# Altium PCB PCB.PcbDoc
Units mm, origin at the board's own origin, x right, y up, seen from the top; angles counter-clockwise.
Board outline 41 x 25.36 mm, 2 copper layers (TOP, BOTTOM), stack 1.586 mm thick; 29 components, 7 nets, 60 pads, 41 vias.
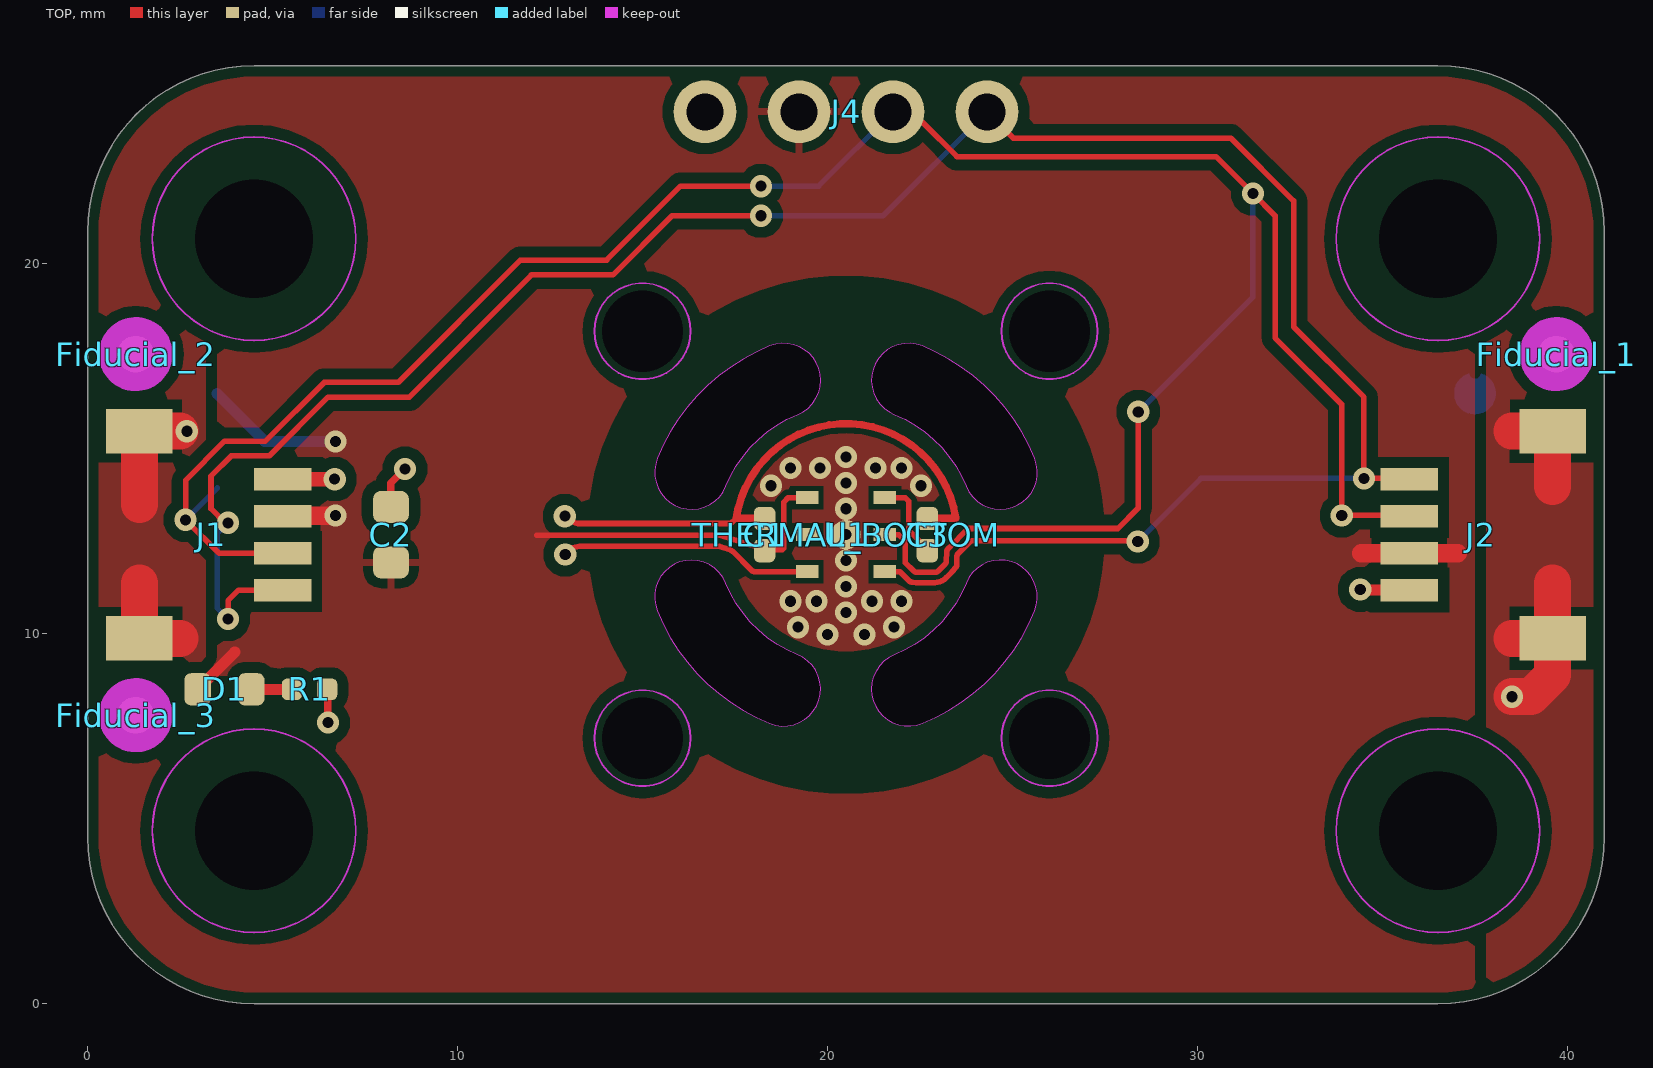
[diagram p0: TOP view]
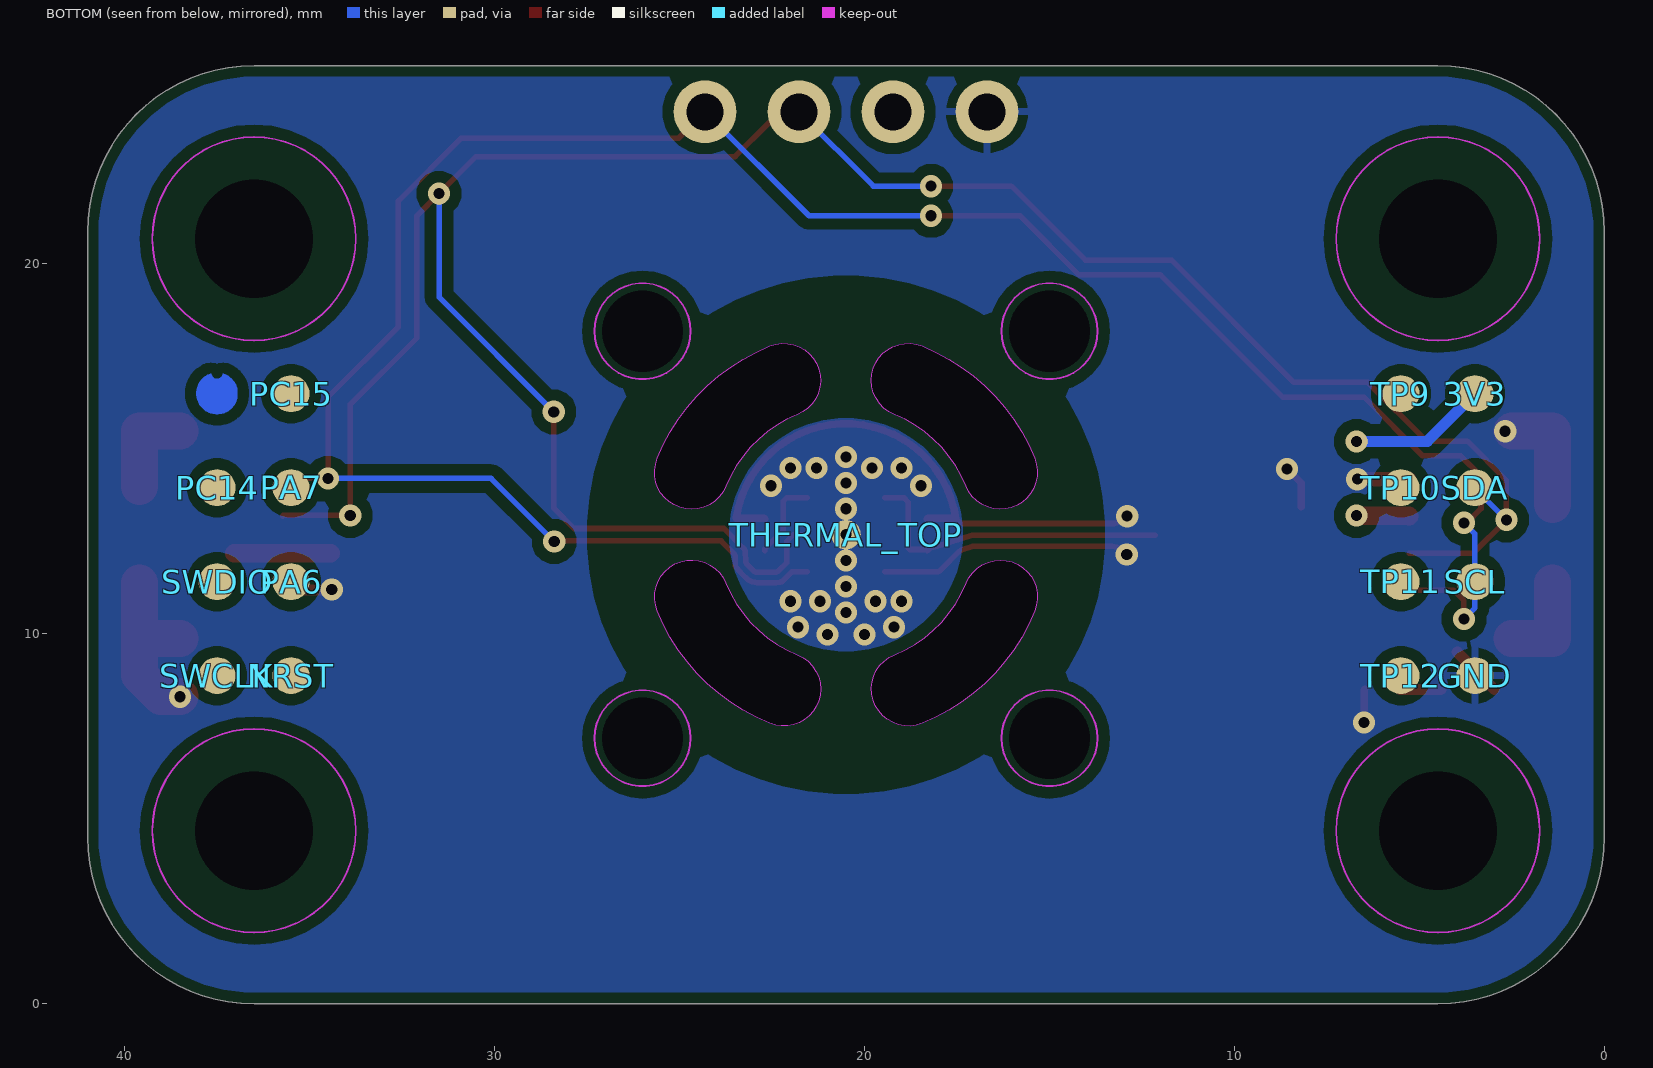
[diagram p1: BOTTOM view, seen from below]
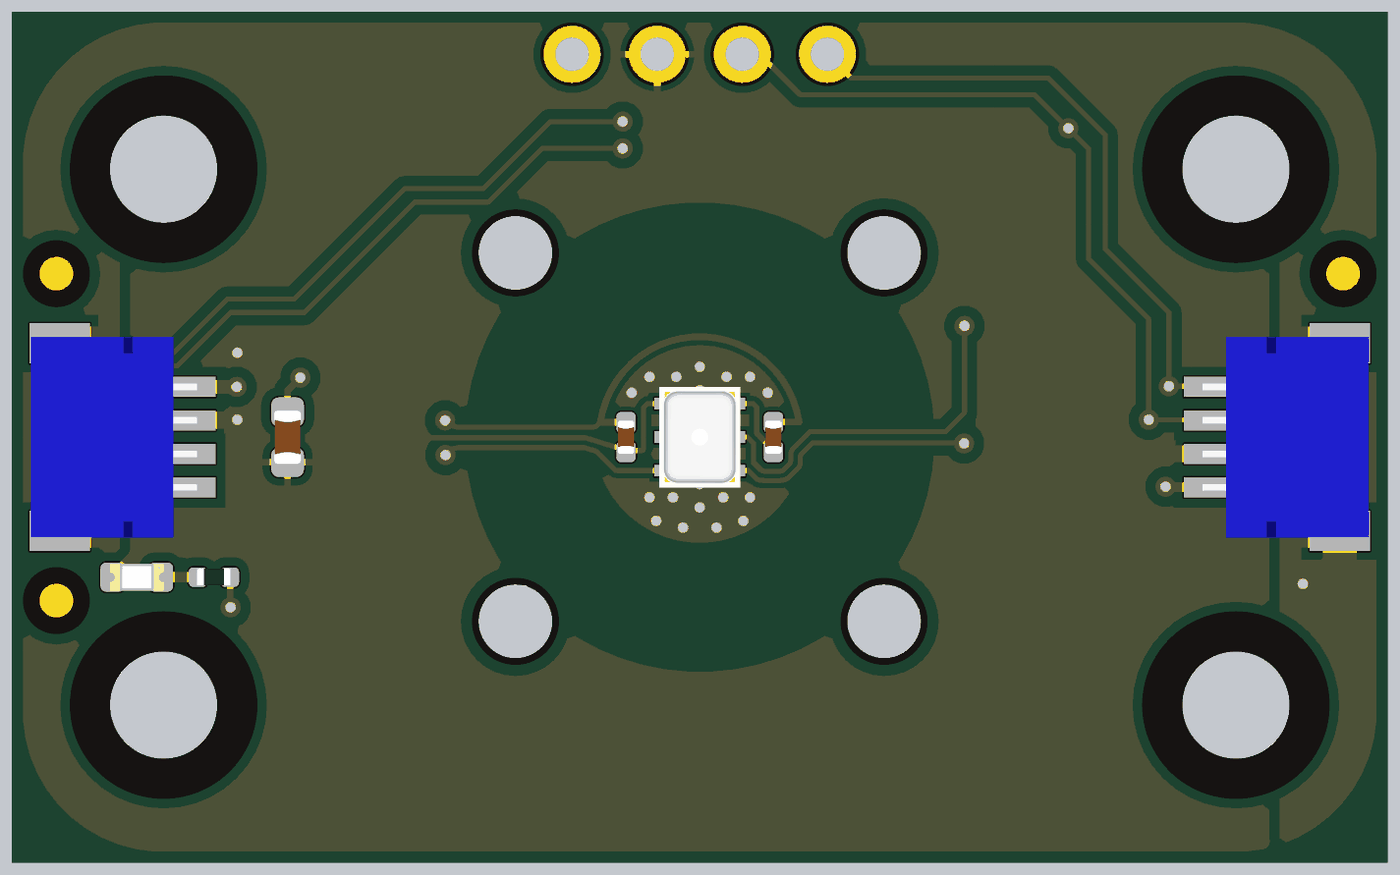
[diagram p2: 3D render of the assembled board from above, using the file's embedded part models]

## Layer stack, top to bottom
Top Solder: solder mask 0.01, Solder Resist, Dk 3.5
TOP: signal copper 0.018
Dielectric: core 1.55, FR-4, Dk 4.8
BOTTOM: signal copper 0.018
Bottom Solder: solder mask 0.01, Solder Resist, Dk 3.5

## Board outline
0,4.5 ccw(c4.5,4.5) 4.5,0 36.5,0 ccw(c36.5,4.5) 41,4.5 41,20.86 ccw(c36.5,20.86) 36.5,25.36 4.5,25.36 ccw(c4.5,20.86) 0,20.86
cut-out: 25.6,10.62 ccw(c24.672,10.994) 23.745,11.369 cw(c20.5,12.68) 21.811,9.435 ccw(c22.186,8.508) 21.185,8.508 ccw(c22.186,8.508) 22.561,7.58 ccw(c20.5,12.68)
cut-out: 22.561,17.78 ccw(c22.186,16.852) 21.811,15.925 cw(c20.5,12.68) 23.745,13.991 ccw(c24.672,14.366) 24.672,13.365 ccw(c24.672,14.366) 25.6,14.74 ccw(c20.5,12.68)
cut-out: 18.44,7.58 ccw(c18.814,8.508) 19.189,9.435 cw(c20.5,12.68) 17.255,11.369 ccw(c16.328,10.994) 16.328,11.995 ccw(c16.328,10.994) 15.4,10.62 ccw(c20.5,12.68)
cut-out: 15.4,14.74 ccw(c16.328,14.366) 17.255,13.991 cw(c20.5,12.68) 19.189,15.925 ccw(c18.814,16.852) 19.815,16.852 ccw(c18.814,16.852) 18.44,17.78 ccw(c20.5,12.68)

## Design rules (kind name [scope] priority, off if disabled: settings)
BoardOutlineClearance Mousebites [(ObjectKind = 'Pad') And (Name = 'Free-MOUSEBITE')] p1: gap=0 ignorepadtopadclearanceinfootprint=FALSE
BoardOutlineClearance Silks [(OnLayer('Top Overlay') OR OnLayer('Bottom Overlay'))] p2: gap=0 ignorepadtopadclearanceinfootprint=FALSE
BoardOutlineClearance [All] p3: gap=0.3 ignorepadtopadclearanceinfootprint=FALSE
Clearance THERMAL_COPPER [InNet('THERMAL_1')] p1: gap=0.15 ignorepadtopadclearanceinfootprint=TRUE
Clearance COPPER_0.3mm [All] p2: gap=0.127 ignorepadtopadclearanceinfootprint=FALSE except(0.3: Arc-Fill Arc-Poly Arc-Region Track-Fill Track-Poly Track-Region SMDPad-Fill SMDPad-Poly SMDPad-Region THPad-Fill THPad-Poly THPad-Region Via-Fill Via-Poly Via-Region Fill-Fill Fill-Poly Fill-Region Poly-Poly Poly-Region Region-Region)
Clearance "Generic clearance 0.15mm" [All] p3: gap=0.15 ignorepadtopadclearanceinfootprint=FALSE
ComponentClearance [All] p1: gap=0.2 collisioncheckmode=3 verticalgap=0 showdistances=TRUE
DiffPairsRouting USB [InDifferentialPairClass('USB')] p1: maxlimit=0.15 minlimit=0.15 mostfreqgap=0.15 toplayer_minwidth=0.15 toplayer_maxwidth=0.21 toplayer_prefwidth=0.2 bottomlayer_minwidth=0.15 bottomlayer_maxwidth=0.21 bottomlayer_prefwidth=0.2 impedanceprofiledriven=TRUE impedanceprofileid={E6B00C31-4C8E-439C-824F-D2B2CDC26F9C} impedanceprofilevalue=90.000000 maxuncoupledlength=12.7
Height [All] p1: minheight=0 maxheight=30 prefheight=12.7
HoleSize [All] p1: absolutevalues=TRUE maxlimit=30 minlimit=0.3 maxpercent=80.000 minpercent=20.000
HoleToHoleClearance [All] p1: gap=0.25 allowstackedmicrovias=FALSE
MinimumAnnularRing [All] p1: minimumring=0.15
PlaneConnect [All] p1: pad.planeconnectstyle=Relief pad.reliefexpansion=0.508 pad.reliefentries=4 pad.reliefconductorwidth=0.254 pad.reliefairgap=0.254 via.planeconnectstyle=Direct via.reliefexpansion=0.508 via.reliefentries=4 via.reliefconductorwidth=0.254 via.reliefairgap=0.254
PolygonConnect thermal [InNet('THERMAL_1') vs InNet('THERMAL_1')] p1: connectstyle=Direct reliefconductorwidth=0.254 reliefentries=4 polygonreliefangle="90 Angle" airgapwidth=0.254
PolygonConnect [All] p2: thpad.connectstyle=Relief thpad.reliefconductorwidth=0.2 thpad.reliefentries=4 thpad.polygonreliefangle="90 Angle" thpad.airgapwidth=0.254 smdpad.connectstyle=Relief smdpad.reliefconductorwidth=0.2 smdpad.reliefentries=4 smdpad.polygonreliefangle="90 Angle" smdpad.airgapwidth=0.254 via.connectstyle=Direct via.reliefconductorwidth=0.254 via.reliefentries=4 via.polygonreliefangle="90 Angle" via.airgapwidth=0.254
RoomDefinition TOP [InComponentClass('TOP')] p1: confinementstyle=ConfineIn formatcopy=TRUE lockcomponents=FALSE outline 45.5,3 55,3 55,20 45.5,20
RoutingVias StandardVias [All] p1: holewidth=0.3 width=0.6 viastyle="Through Hole" minholewidth=0.3 minwidth=0.6 maxholewidth=0.3 maxwidth=0.6
SMDToCorner [All] p1: distance=39370
SilkToSilkClearance [All] p1: silktosilkclearance=0.2
SilkToSolderMaskClearance [IsPad] p1: minsilkscreentomaskgap=0.15 clearancetoexposedcopper=TRUE
SolderMaskExpansion VIAtented [IsVia] p1: expansion=0.102 istentingtop=TRUE
SolderMaskExpansion [All] p2: expansion=0.05 istentingtop=FALSE
UnConnectedPin [All] p1:
UnRoutedNet [not WithinRoom('K36')] p1: checkbadconnections=TRUE
ViasUnderSMD [All] p1: allowed=FALSE
Width StandardTraces [All] p1: maxlimit=5 minlimit=0.15 preferedwidth=0.15 minimp=50.000000 maximp=50.000000 favimp=50.000000
21 further rules are at their usual default settings.

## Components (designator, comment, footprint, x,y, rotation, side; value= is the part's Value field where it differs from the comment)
3V3 "Test point 1.00mm" TP-1.00MM 3.5,16.49 r90 bottom
C1 "0402B104K160CT" CAP-0402 18.3,12.68 r90 top value=100nF
C2 "GRM188R61C475KAAJD" CAP-0603 8.2,12.68 r270 top value=4.7µF
C3 "0402B104K160CT" CAP-0402 22.7,12.68 r90 top value=100nF
D1 "HSMG-C190" LEDC1608X80N-AK 3.7,8.5 r180 top
Fiducial_1 "Fiducial mark 1mm" "Fiducial mark 1mm-Footprint-1" 39.7,17.56 r270 top
Fiducial_2 "Fiducial mark 1mm" "Fiducial mark 1mm-Footprint-1" 1.3,17.56 r270 top
Fiducial_3 "Fiducial mark 1mm" "Fiducial mark 1mm-Footprint-1" 1.3,7.8 r270 top
GND "Test point 1.00mm" TP-1.00MM 3.5,8.87 r90 bottom
J1 "SM04B-SRSS-TB(LF)(SN)" SM04B-SRSS-TB(LF)(SN)-Footprint-1 3.337,12.68 r90 top locked
J2 "SM04B-SRSS-TB(LF)(SN)" SM04B-SRSS-TB(LF)(SN)-Footprint-1 37.663,12.68 r270 top locked
J4 "HEADER TH 2.54mm VERT. 1x004POS" "PIN HEADER 2.54mm VERT. 1x4POS-Footprint-1" 20.5,24.11 r0 top
NRST "Test point 1.00mm" TP-1.00MM 35.5,8.87 r180 bottom
PA6 "Test point 1.00mm" TP-1.00MM 35.5,11.41 r180 bottom
PA7 "Test point 1.00mm" TP-1.00MM 35.5,13.95 r180 bottom
PC14 "Test point 1.00mm" TP-1.00MM 37.5,13.95 r180 bottom
PC15 "Test point 1.00mm" TP-1.00MM 35.5,16.49 r180 bottom
R1 "CRCW04021K00FKEDC" RES-0402 6,8.5 r180 top value=1k
SCL "Test point 1.00mm" TP-1.00MM 3.5,11.41 r90 bottom
SDA "Test point 1.00mm" TP-1.00MM 3.5,13.95 r90 bottom
SWCLK "Test point 1.00mm" TP-1.00MM 37.5,8.87 r180 bottom
SWDIO "Test point 1.00mm" TP-1.00MM 37.5,11.41 r180 bottom
THERMAL_BOTTOM "CMP-018-0004-A.4" TP-0.8MM 20.5,12.68 r90 top
THERMAL_TOP "CMP-018-0004-A.4" TP-0.8MM 20.5,12.68 r90 bottom
TP9 "Test point 1.00mm" TP-1.00MM 5.5,16.49 r0 bottom
TP10 "Test point 1.00mm" TP-1.00MM 5.5,13.95 r0 bottom
TP11 "Test point 1.00mm" TP-1.00MM 5.5,11.41 r0 bottom
TP12 "Test point 1.00mm" TP-1.00MM 5.5,8.87 r0 bottom
U1 "HS3003" HS3003-Footprint-1 20.5,12.68 r90 top

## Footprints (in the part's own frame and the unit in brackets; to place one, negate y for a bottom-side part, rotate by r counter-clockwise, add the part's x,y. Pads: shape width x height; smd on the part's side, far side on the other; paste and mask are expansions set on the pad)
CAP-0402 [mm] "Chip Capacitor, 2-Leads, Body  0402 (in) 1005 (mm), IPC Medium Density"
  rrect52% 0.63x0.58 smd mask+0.05: 1(-0.435,0) 2(0.435,0)
  body extent -0.5,-0.25 0.5,0.25, height 0.5
CAP-0603 [mm] "Chip Capacitor, Body 0603 imperial,1.6x0.8mm, IPC High Density"
  rrect51% 0.87x0.97 smd mask+0.05: 1(-0.75,0) 2(0.75,0)
  body extent -0.8,-0.4 0.8,0.4, height 0.8
"Fiducial mark 1mm-Footprint-1" [mm]
  round 1 smd paste-10 mask+0.5: 1(0,0)
  TOP keep-out circle w1: c0,0 r0.5
HS3003-Footprint-1 [mm]
  rect 0.35x0.61 smd mask+0.05: 1(-1,-1.05) 2(0,-1.05) 3(1,-1.05) 4(1,1.05) 5(0,1.05) 6(-1,1.05)
  body extent -1.5,-1.2 1.5,1.2, height 0.9
LEDC1608X80N-AK [mm]
  rrect50% 0.72x0.87 smd: A(0.725,0) C(-0.725,0)
  body extent -0.8,-0.4 0.8,0.4, height 0.79
"PIN HEADER 2.54mm VERT. 1x4POS-Footprint-1" [mm]
  round 1.7 hole 1 mask+0.1: 1(-3.81,0) 2(-1.27,0) 3(1.27,0) 4(3.81,0)
RES-0402 [mm] "Chip Resistor, 2-Leads, Body  0402 (in) 1005 (mm), IPC Medium Density"
  rrect51% 0.55x0.58 smd mask+0.05: 1(-0.475,0) 2(0.475,0)
  body extent -0.5,-0.25 0.5,0.25, height 0.34
SM04B-SRSS-TB(LF)(SN)-Footprint-1 [mm]
  rect 0.6x1.55 smd mask+0.05: 1(1.5,-1.937) 2(0.5,-1.937) 3(-0.5,-1.937) 4(-1.5,-1.937)
  rect 1.2x1.8 smd mask+0.05: FIX(-2.8,1.938) FIX(2.8,1.938)
  body extent -3,-2.16 3,2.8, height 2.98
TP-0.8MM [mm]
  rrect100% 0.8x0.8 smd paste-2.54 mask+0.05: X(0,0)
TP-1.00MM [mm]
  rrect100% 1x1 smd paste-2.54: X(0,0)

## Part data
3V3 GND NRST PA6 PA7 PC14 PC15 SCL SDA SWCLK SWDIO TP9 TP10 TP11 TP12: library part UT0013-A.6, Manufacturer="This is not a component"
C1 C3: library part C0012-A.15, "CAP CHIP 0402 100nF 10% 16V X7R", Case Code (Imperial)=0402, Dielectric=X7R, Manufacturer=Walsin, Tolerance=10%, Voltage=16V
C2: library part C0054-A.16, "CAP CHIP 0603 4.7uF 10% 16V X5R", Case Code (Imperial)=0603, Dielectric=X5R, Manufacturer=Murata, Manufacturer 3="Samsung Electro-Mechanics", Part number 2=GRM188R61C475KE11D, Part number 3=CL10A475KO8NNNC, Tolerance=10%, Voltage=16V
D1: library part L0009-A.5, "LED SMD 0603 GREEN/568 15mcd 120^", Manufacturer=Broadcom
Fiducial_1 Fiducial_2 Fiducial_3: library part UT0023-A.7, "Fiducial mark 1mm clearance 2mm"
J1 J2: library part J0005-A.2, "CONN JST 4POS SIDE 1MM TIN QWIIC", Manufacturer=JST
J4: library part J0162-A.5
R1: library part R0007-A.24, "RES CHIP 0402 1k 1% 1/16W", Case Code (Imperial)=0402, Manufacturer=Vishay, Power=62.5mW, Temperature Coefficient=100ppm, Tolerance=1%
THERMAL_BOTTOM THERMAL_TOP: library part UT0012-A.6, "Test point 0.8mm", Manufacturer="This is not a component"
U1: library part U0253-A.5, "IC PRESSURE AND TEMPERATURE SENSOR 6-LGA", Manufacturer=Renesas

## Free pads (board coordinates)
  round 3 hole 3.2 unplated paste-2539.97 mask+1.3: MH(4.5,4.68) MH(4.5,20.68) MH(36.5,4.68) MH(36.5,20.68)
  round 2 hole 2.2 unplated paste-2539.97 mask+0.3: MH(15,7.18) MH(15,18.18) MH(26,7.18) MH(26,18.18)

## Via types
v1: diameter 0.6, hole 0.3, TOP to BOTTOM, tented both sides, 41 vias

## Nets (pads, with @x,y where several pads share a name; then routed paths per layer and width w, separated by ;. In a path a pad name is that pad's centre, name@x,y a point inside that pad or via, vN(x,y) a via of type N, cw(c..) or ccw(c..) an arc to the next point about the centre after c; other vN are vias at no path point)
+3V3: 3V3.X C1.1 C2.2 D1.A J1.2 J2.2 J4.2 U1.4 | length 18
  TOP w0.15: 12.139,12.661 17.092,12.661 17.902,12.407 C1.1@18.23,12.305 ; C1.1@18.161,12.364 C1.1@18.23,12.305 ; U1.4 18.939,13.68 18.82,13.56 18.82,12.317 18.783,12.28 18.335,12.28 C1.1 C1.1@18.23,12.305
  TOP w0.3: D1.A 3.98,9.505
  TOP w0.5: J1.2 5.284,13.19 6.69,13.19 v1(6.7,13.2) ; 34.42,12.18 J2.2 37.031,12.18
  BOTTOM w0.3: 3V3.X 4.79,15.2 v1(6.7,15.2)
GND: C1.2 C2.1 C3.2 GND.X J1.1 J1.FIX J2.1 J2.FIX J4.1 R1.1 U1.6 | length 41.3
  TOP w0.15: v1@12.867,13.223 ccw(c12.988,13.311) v1@12.868,13.221 ; v1(12.9,13.18) 12.939,13.111 ccw(c13.069,13.186) 13.029,13.042 13.227,12.987 ccw(c13.267,13.132) 13.267,12.982 17.329,12.982 ccw(c17.329,13.132) 17.435,13.026 17.533,13.123 ; v1(12.912,12.147) 12.996,12.268 cw(c13.119,12.182) 13.093,12.33 13.301,12.367 ; 13.327,12.37 ccw(c13.327,12.22) 13.301,12.367 ; 15.527,12.37 15.8,12.37 ; U1.6 18.045,11.68 cw(c18.045,11.83) 17.939,11.724 17.428,12.235 ccw(c17.321,12.129) 17.365,12.273 17.07,12.363 ccw(c17.026,12.22) 17.026,12.37 15.8,12.37 ; 13.301,12.367 15.798,12.367 15.8,12.37
  TOP w0.2: R1.1 6.488,8.488 6.488,7.612 v1(6.5,7.6) ; C2.1 8.2,14.076 v1(8.581,14.456) ; C1.2 18.292,13.123 17.533,13.123 cw(c20.5,12.68) 20.637,15.677 cw(c20.5,12.68) 23.466,13.129 22.733,13.129 ccw(c22.733,13.082) C3.2
  TOP w0.3: v1(34.4,11.2) 34.41,11.19 35.716,11.19 J2.1
  TOP w0.4: J1.1 v1(6.68,14.18)
  TOP w0.5: J1.FIX@1.399,15.48 2.678,15.48 v1(2.683,15.475)
  TOP w1: 1.399,11.379 1.399,9.88 2.5,9.88 ; 1.399,13.499 1.399,15.48 v1@2.5,15.48 ; 38.499,9.881 39.6,9.881 39.6,11.38 ; v1(38.5,8.3) 39.015,8.3 39.601,8.886 J2.FIX@39.601,9.88 ; 38.5,15.48 39.601,15.48 39.601,13.981
NetC3_1: C3.1 U1.3 | length 2.2
  TOP w0.15: U1.3 22.1,13.68 22.2,13.58 22.2,12.794 22.7,12.294 C3.1
NetD1_C: D1.C R1.2 | length 1.1
  TOP w0.3: D1.C R1.2
SCL_1: J1.4 J2.4 J4.4 SCL.X U1.1 | length 64.7
  TOP w0.15: v1(3.8,10.4) 3.8,10.9 4.08,11.18 J1.4 ; v1(3.8,13) 3.723,13 3.337,13.386 3.337,14.262 3.888,14.813 4.913,14.813 6.5,16.4 8.7,16.4 12,19.7 14.2,19.7 15.8,21.3 v1(18.2,21.3) ; U1.1 21.953,11.68 22.196,11.437 ccw(c22.302,11.543) 22.291,11.393 22.394,11.386 ccw(c22.425,11.812) 22.425,11.385 22.897,11.385 ccw(c22.897,11.812) 23.198,11.509 23.366,11.677 ccw(c23.064,11.978) 23.385,11.697 23.457,11.779 ccw(c23.344,11.878) 23.494,11.876 23.494,12.072 cw(c23.644,12.072) 23.538,12.178 23.873,12.513 28.365,12.513 v1(28.387,12.492) ; J4.4 25.02,23.4 30.9,23.4 32.6,21.7 32.6,18.3 34.5,16.4 v1(34.5,14.2) 35.706,14.2 J2.4
  BOTTOM w0.15: v1(3.8,10.4) 3.5,10.7 SCL.X 3.5,12.7 v1(3.8,13) ; v1(18.2,21.3) 21.5,21.3 J4.4 ; v1(28.387,12.492) 30.095,14.2 v1(34.5,14.2)
SDA_1: J1.3 J2.3 J4.3 SDA.X U1.2 | length 69
  TOP w0.15: J1.3 3.897,12.18 3.895,12.178 3.554,12.178 v1(2.65,13.082) 2.65,14.15 3.707,15.207 4.807,15.207 6.4,16.8 8.4,16.8 11.7,20.1 14.03,20.1 16.03,22.1 v1(18.2,22.1) ; U1.2 21.922,12.68 22.105,12.497 22.105,11.92 22.319,11.706 22.32,11.705 ccw(c22.425,11.812) 22.425,11.662 22.897,11.662 ccw(c22.897,11.812) 23.003,11.705 23.17,11.872 ccw(c23.064,11.978) 23.213,11.973 23.221,12.209 cw(c23.371,12.204) 23.265,12.31 23.802,12.847 27.847,12.847 28.4,13.4 v1(28.4,16) ; J4.3 22.067,23.813 22.587,23.813 23.5,22.9 30.5,22.9 v1(31.5,21.9) 32.1,21.3 32.1,18 33.9,16.2 v1(33.9,13.2) 35.706,13.2 J2.3
  BOTTOM w0.15: v1(2.65,13.082) 3.5,13.932 SDA.X ; v1(18.2,22.1) 19.76,22.1 J4.3 ; v1(28.4,16) 31.5,19.1 v1(31.5,21.9)
THERMAL_1: THERMAL_BOTTOM.X THERMAL_TOP.X
  other v1: 20,9.98 21,9.98 19.2,10.18 21.8,10.18 20.5,10.58 19,10.88 19.7,10.88 21.2,10.88 22,10.88 20.5,11.28 20.5,11.98 20.5,12.68 20.5,13.38 18.47,14.004 22.53,14.004 20.5,14.08 19,14.48 19.8,14.48 21.3,14.48 22,14.48 20.5,14.78
pads on no net: Fiducial_1.1 Fiducial_2.1 Fiducial_3.1 NRST.X PA6.X PA7.X PC14.X PC15.X SWCLK.X SWDIO.X TP9.X TP10.X TP11.X TP12.X U1.5

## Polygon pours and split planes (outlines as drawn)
+3V3 on TOP "NONET_L04_P-001" (solid, remove dead copper, pour order 11): 0,4.5 ccw(c4.5,4.5) 4.5,0 36.5,0 ccw(c36.5,4.5) 41,4.5 41,20.86 ccw(c36.5,20.86) 36.5,25.36 4.5,25.36 ccw(c4.5,20.86) 0,20.86
THERMAL_1 on TOP "THERMAL_1_L01_P001" (solid, remove dead copper, pour order 1): 17.35,12.68 ccw(c20.5,12.68) 20.5,9.53 ccw(c20.5,12.68) 23.65,12.68 ccw(c20.5,12.68) 20.5,15.83 ccw(c20.5,12.68)
GND on TOP "NONET_L04_P-001" (solid, remove dead copper, pour order 7): 0,25.36 0,0 3.2,0 3.2,25.36
GND on TOP "NONET_L04_P-001" (solid, remove dead copper, pour order 5): 41,25.36 41,0 37.8,0 37.8,25.36
GND on BOTTOM "NONET_L04_P-001" (solid, remove dead copper, pour order 12): 0,4.5 ccw(c4.5,4.5) 4.5,0 36.5,0 ccw(c36.5,4.5) 41,4.5 41,20.86 ccw(c36.5,20.86) 36.5,25.36 4.5,25.36 ccw(c4.5,20.86) 0,20.86
THERMAL_1 on BOTTOM "THERMAL_1_L02_P008" (solid, remove dead copper, pour order 8): 17.35,12.68 ccw(c20.5,12.68) 20.5,9.53 ccw(c20.5,12.68) 23.65,12.68 ccw(c20.5,12.68) 20.5,15.83 ccw(c20.5,12.68)

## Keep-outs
Keep-Out Layer:
  circle w0.05: c15,18.18 r1.3
  circle w0.05: c26,18.18 r1.3
  circle w0.05: c26,7.18 r1.3
  circle w0.05: c15,7.18 r1.3
  circle w0.05: c36.5,4.68 r2.75
  circle w0.05: c36.5,20.68 r2.75
  circle w0.05: c4.5,4.68 r2.75
  circle w0.05: c4.5,20.68 r2.75

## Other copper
TOP:
  pour cut-out: 24,12.68 cw(c20.5,12.68) 20.5,9.18 20.5,5.68 ccw(c20.5,12.68) 27.5,12.68
  pour cut-out: 20.5,9.18 cw(c20.5,12.68) 17,12.68 13.5,12.68 ccw(c20.5,12.68) 20.5,5.68
  pour cut-out: 17,12.68 cw(c20.5,12.68) 20.5,16.18 20.5,19.68 ccw(c20.5,12.68) 13.5,12.68
  pour cut-out: 20.5,16.18 cw(c20.5,12.68) 24,12.68 27.5,12.68 ccw(c20.5,12.68) 20.5,19.68
BOTTOM:
  pour cut-out: 20.5,16.18 cw(c20.5,12.68) 24,12.68 27.5,12.68 ccw(c20.5,12.68) 20.5,19.68
  pour cut-out: 17,12.68 cw(c20.5,12.68) 20.5,16.18 20.5,19.68 ccw(c20.5,12.68) 13.5,12.68
  pour cut-out: 20.5,9.18 cw(c20.5,12.68) 17,12.68 13.5,12.68 ccw(c20.5,12.68) 20.5,5.68
  pour cut-out: 24,12.68 cw(c20.5,12.68) 20.5,9.18 20.5,5.68 ccw(c20.5,12.68) 27.5,12.68
  region: 589 vertices and 0 holes, not listed, extent 36.947,15.938 38.059,17.027

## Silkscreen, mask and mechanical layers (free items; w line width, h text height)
Bottom Solder:
  region: 17.35,12.68 ccw(c20.5,12.68) 20.5,9.53 ccw(c20.5,12.68) 23.65,12.68 ccw(c20.5,12.68) 20.5,15.83 ccw(c20.5,12.68)
Route Tool Path:
  lines w2: -1,8.498 -1,16.86 ; 16.328,10.994 ccw(c20.5,12.68) 18.814,8.508 ; 16.328,14.366 cw(c20.5,12.68) 18.814,16.852 ; 22.186,8.508 ccw(c20.5,12.68) 24.672,10.994 ; 22.186,16.852 cw(c20.5,12.68) 24.672,14.366 ; 42,4.5 cw(c36.5,4.5) 36.5,-1 ; 42,8.498 42,16.86 ; -1,4.498 ccw(c4.5,4.5) 4.498,-1 ; -1,4.498 cw(c4.5,4.5) -1,4.5 ccw(c0,4.5) -1,4.498 ; -1,20.86 cw(c4.5,20.86) 4.5,26.36 ; -1,20.86 -1,20.86 ; 4.498,-1 ccw(c4.5,4.5) 4.5,-1 ; 4.498,-1 ccw(c4.5,0) 4.5,-1 ; 4.5,-1 36.5,-1 ; 4.5,26.36 36.5,26.36 ; 4.5,26.36 4.5,26.36 ; 36.5,-1 36.5,-1 ; 36.5,26.36 cw(c36.5,20.86) 36.502,26.36 ; 36.5,26.36 cw(c36.5,25.36) 36.502,26.36 ; 36.502,26.36 cw(c36.5,20.86) 42,20.863 ; 42,20.863 cw(c41,20.86) 42,20.86 ccw(c36.5,20.86) 42,20.863
Board:
  the board outline again, w0.05
Mechanical 33:
  lines w0.05: 8.44,1.25 9.07,1.25 ; 9.07,0.62 9.07,1.25 ; 9.07,1.88 9.07,1.25 ; 9.7,1.25 9.07,1.25 ; 10.98,1.25 11.61,1.25 ; 11.61,0.62 11.61,1.25 ; 11.61,1.88 11.61,1.25 ; 12.24,1.25 11.61,1.25 ; 13.52,1.25 14.15,1.25 ; 14.15,0.62 14.15,1.25 ; 14.15,1.88 14.15,1.25 ; 14.78,1.25 14.15,1.25 ; 16.06,1.25 16.69,1.25 ; 16.06,24.11 16.69,24.11 ; 16.69,0.62 16.69,1.25 ; 16.69,1.88 16.69,1.25 ; 16.69,23.48 16.69,24.11 ; 16.69,24.74 16.69,24.11 ; 17.32,1.25 16.69,1.25 ; 17.32,24.11 16.69,24.11 ; 18.6,1.25 19.23,1.25 ; 18.6,24.11 19.23,24.11 ; 19.23,0.62 19.23,1.25 ; 19.23,1.88 19.23,1.25 ; 19.23,23.48 19.23,24.11 ; 19.23,24.74 19.23,24.11 ; 19.86,1.25 19.23,1.25 ; 19.86,24.11 19.23,24.11 ; 21.14,1.25 21.77,1.25 ; 21.14,24.11 21.77,24.11 ; 21.77,0.62 21.77,1.25 ; 21.77,1.88 21.77,1.25 ; 21.77,23.48 21.77,24.11 ; 21.77,24.74 21.77,24.11 ; 22.4,1.25 21.77,1.25 ; 22.4,24.11 21.77,24.11 ; 23.68,1.25 24.31,1.25 ; 23.68,24.11 24.31,24.11 ; 24.31,0.62 24.31,1.25 ; 24.31,1.88 24.31,1.25 ; 24.31,23.48 24.31,24.11 ; 24.31,24.74 24.31,24.11 ; 24.94,1.25 24.31,1.25 ; 24.94,24.11 24.31,24.11 ; 26.22,1.25 26.85,1.25 ; 26.85,0.62 26.85,1.25 ; 26.85,1.88 26.85,1.25 ; 27.48,1.25 26.85,1.25 ; 28.76,1.25 29.39,1.25 ; 29.39,0.62 29.39,1.25 ; 29.39,1.88 29.39,1.25 ; 30.02,1.25 29.39,1.25 ; 31.3,1.25 31.93,1.25 ; 31.93,0.62 31.93,1.25 ; 31.93,1.88 31.93,1.25 ; 32.56,1.25 31.93,1.25
Mechanical 66:
  circle w0.05: c36.5,4.68 r2.85
  circle w0.05: c36.5,20.68 r2.85
  circle w0.05: c4.5,20.68 r2.85
  circle w0.05: c4.5,4.68 r2.85
thermal:
  circle w0.05: c20.5,12.68 r3.15
  lines w0.05: 20.5,16.18 cw(c20.5,12.68) 24,12.68 27.5,12.68 ccw(c20.5,12.68) 20.5,19.68 20.5,16.18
